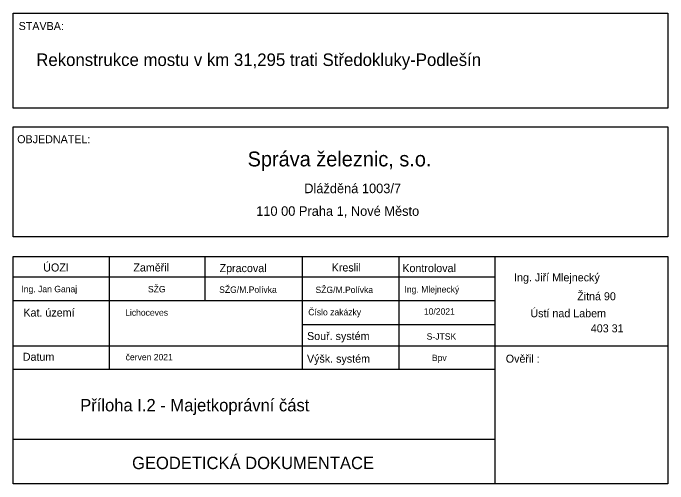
# Model space of a CAD drawing. Extents: x -879530 to -879371, y -1019242 to -1019127.
import ezdxf

# ---------------------------------------------------------------- set-up
doc = ezdxf.new("R2010")
doc.units = 0
doc.layers.add('tabulka', color=7, linetype='Continuous')

msp = doc.modelspace()

# ---------------------------------------------------------------- linework, layer by layer
at = {"layer": 'tabulka'}
for p, q in [((-879530.09, -1019186.45), (-879371.44, -1019186.45)), ((-879506.8, -1019186.45), (-879506.8, -1019213.77)), ((-879483.66, -1019186.45), (-879483.66, -1019197.07)), ((-879460.06, -1019186.45), (-879460.06, -1019213.77)), ((-879436.61, -1019186.45), (-879436.61, -1019213.77)), ((-879413.31, -1019241.58), (-879413.31, -1019186.45)), ((-879530.09, -1019191.36), (-879413.31, -1019191.36)), ((-879530.09, -1019197.07), (-879413.31, -1019197.07)), ((-879460.06, -1019202.88), (-879413.31, -1019202.88)), ((-879530.09, -1019208.07), (-879371.44, -1019208.07)), ((-879530.09, -1019213.77), (-879413.31, -1019213.77)), ((-879530.09, -1019230.76), (-879413.31, -1019230.76))]:
    msp.add_line(p, q, dxfattribs=at)
for points in [[(-879530.09, -1019127.36), (-879371.44, -1019127.36), (-879371.44, -1019150.43), (-879530.09, -1019150.43)], [(-879530.09, -1019154.95), (-879371.44, -1019154.95), (-879371.44, -1019181.64), (-879530.09, -1019181.64)]]:
    msp.add_lwpolyline(points, close=True, dxfattribs=at)
msp.add_lwpolyline([(-879371.44, -1019186.45), (-879371.44, -1019241.58), (-879530.09, -1019241.58), (-879530.09, -1019186.45)], dxfattribs=at)

# ---------------------------------------------------------------- texts
for s, height, p in [('STAVBA:', 1.94, (-879528.75, -1019131.47)), ('Rekonstrukce mostu v km 31,295 trati Středokluky-Podlešín', 3.04, (-879524.48, -1019140.2)), ('OBJEDNATEL:', 1.94, (-879529.1, -1019158.93)), ('Správa železnic, s.o.', 3.61, (-879473.27, -1019164.56)), ('Dlážděná 1003/7', 2.32, (-879459.55, -1019171.05)), ('110 00 Praha 1, Nové Město', 2.32, (-879471.19, -1019176.55)), ('ÚOZI', 1.94, (-879522.79, -1019190.05)), ('Zaměřil', 1.94, (-879500.95, -1019190.05)), ('Zpracoval', 1.94, (-879480.06, -1019190.2)), ('Kreslil', 1.94, (-879452.9, -1019190.05)), ('Kontroloval', 1.94, (-879435.78, -1019190.2)), ('Ing. Jiří Mlejnecký', 1.94, (-879408.71, -1019192.45)), ('Ing. Jan Ganaj', 1.552, (-879528.08, -1019195.08)), ('SŽG', 1.552, (-879497.41, -1019195.11)), ('SŽG/M.Polívka', 1.552, (-879480.16, -1019195.23)), ('SŽG/M.Polívka', 1.552, (-879456.82, -1019195.27)), ('Ing. Mlejnecký', 1.552, (-879435.26, -1019195.15)), ('Žitná 90', 1.94, (-879393.42, -1019197.03)), ('Kat. území', 1.94, (-879527.6, -1019200.99)), ('Lichoceves', 1.552, (-879502.94, -1019200.79)), ('Číslo zakázky', 1.552, (-879458.58, -1019200.7)), ('10/2021', 1.552, (-879430.56, -1019200.52)), ('Ústí nad Labem', 1.94, (-879404.75, -1019201.15)), ('403 31', 1.94, (-879390.12, -1019204.81)), ('Souř. systém', 1.94, (-879458.87, -1019206.68)), ('S-JTSK', 1.552, (-879429.88, -1019206.59)), ('Datum', 1.94, (-879527.74, -1019211.71)), ('červen 2021', 1.552, (-879502.82, -1019211.6)), ('Výšk. systém', 1.94, (-879458.89, -1019212.17)), ('Bpv', 1.552, (-879428.62, -1019211.78)), ('Ověřil :', 1.94, (-879410.72, -1019212.17)), ('Příloha I.2 - Majetkoprávní část', 3, (-879513.83, -1019223.98)), ('GEODETICKÁ DOKUMENTACE ', 3, (-879501.27, -1019237.99))]:
    msp.add_text(s, height=height, dxfattribs=at).set_placement(p)

doc.saveas('drawing.dxf')
